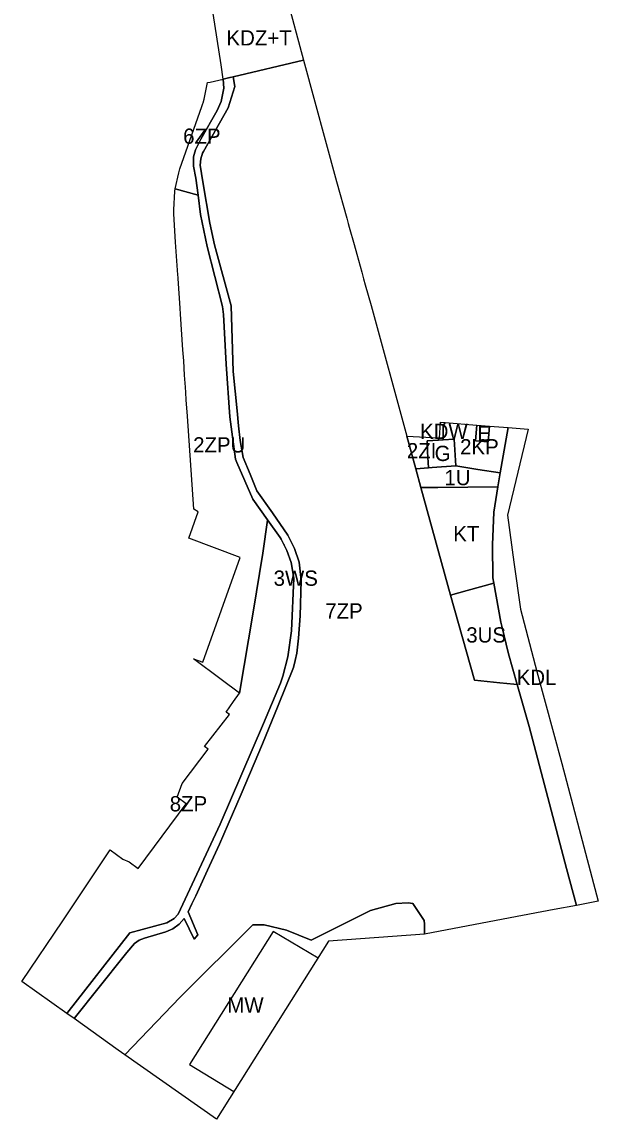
# Model space of a CAD drawing. Extents: x 7428426 to 7429844, y 5541841 to 5543687.
# Drawn here: x 7429103 to 7429555, y 5541841 to 5542703 of the extents above; entities that cross this region are included whole.
import ezdxf

# ---------------------------------------------------------------- set-up
doc = ezdxf.new("R2010")
doc.units = 0
for name, color, linetype in [('1', 7, 'Continuous'), ('linie_rozgraniczajace', 7, 'Continuous'), ('linie_zabudowy_nieprzekraczalne', 7, 'Continuous'), ('oznaczenia_przeznaczen', 7, 'Continuous')]:
    doc.layers.add(name, color=color, linetype=linetype)

msp = doc.modelspace()

# ---------------------------------------------------------------- linework, layer by layer
at = {"layer": '1'}
msp.add_lwpolyline([(7429335.26, 5541967.68), (7429299.84, 5541988.79), (7429234.14, 5541884.33), (7429269, 5541863.04)], dxfattribs=at)
at = {"layer": 'linie_rozgraniczajace'}
for points in [[(7429252.71, 5542709.77), (7429263.73, 5542712.33), (7429269.92, 5542713.77), (7429280.21, 5542716.17), (7429290.51, 5542718.57), (7429295.5, 5542719.72), (7429300.49, 5542720.88), (7429305.48, 5542722.04), (7429310.47, 5542723.2), (7429323.78, 5542673.23), (7429268.47, 5542660.17), (7429266.16, 5542659.62), (7429265.93, 5542659.56), (7429260.77, 5542658.35), (7429259, 5542669.65)], [(7429252.71, 5542709.77), (7429263.73, 5542712.33), (7429269.92, 5542713.77), (7429280.21, 5542716.17), (7429290.51, 5542718.57), (7429295.5, 5542719.72), (7429300.49, 5542720.88), (7429305.48, 5542722.04), (7429310.47, 5542723.2), (7429323.78, 5542673.23), (7429268.47, 5542660.17), (7429266.16, 5542659.62), (7429265.93, 5542659.56), (7429260.77, 5542658.35), (7429259, 5542669.65)], [(7429143.63, 5541920.29), (7429182.91, 5541969.66), (7429184.96, 5541972.29), (7429191.03, 5541979.29), (7429194.73, 5541981.82), (7429198.89, 5541983.54), (7429215.6, 5541988.57), (7429221.15, 5541990.93), (7429226.08, 5541994.41), (7429230.14, 5541998.87), (7429237.89, 5541982.83), (7429240.69, 5541986), (7429233.14, 5542004.12), (7429236.14, 5542010.42), (7429239.15, 5542016.72), (7429248.43, 5542036.98), (7429257.71, 5542057.24), (7429274.67, 5542096.7), (7429291.63, 5542136.15), (7429303.77, 5542166.16), (7429315.9, 5542196.16), (7429317.18, 5542201.74), (7429318.46, 5542207.32), (7429319.96, 5542219.28), (7429321.14, 5542236.59), (7429322.01, 5542264.55), (7429320.38, 5542278.77), (7429316.66, 5542289.62), (7429311.47, 5542300.09), (7429299.34, 5542317.53), (7429287.21, 5542334.96), (7429281.81, 5542348.02), (7429276.42, 5542361.07), (7429273.9, 5542374.36), (7429272.75, 5542386), (7429271.6, 5542397.63), (7429268.55, 5542428.61), (7429266.87, 5542480.27), (7429253.72, 5542528.1), (7429250.27, 5542545.25), (7429244.57, 5542577.78), (7429242.63, 5542590.86), (7429243.15, 5542595.67), (7429244.3, 5542600.11), (7429245.08, 5542601.55), (7429264.64, 5542635.66), (7429269.78, 5542652.45), (7429268.47, 5542660.17), (7429323.78, 5542673.23), (7429349.74, 5542578.03), (7429357.73, 5542549.11), (7429358.9, 5542544.89), (7429359.66, 5542542.13), (7429363.45, 5542528.43), (7429365.56, 5542520.79), (7429366.85, 5542516.09), (7429369.48, 5542506.62), (7429370.92, 5542501.38), (7429372.24, 5542496.62), (7429376.85, 5542480.51), (7429404.99, 5542377.87), (7429411.99, 5542352.26), (7429416.04, 5542337.44), (7429439.17, 5542253.02), (7429458.09, 5542186.04), (7429472.93, 5542184.55), (7429478.04, 5542184.04), (7429478.04, 5542184.04), (7429489.03, 5542182.94), (7429491.65, 5542182.68), (7429501.07, 5542149.66), (7429530.4, 5542038.19), (7429538.1, 5542009.2), (7429520.63, 5542005.91), (7429486.19, 5541999.43), (7429418.94, 5541986.7), (7429418.81, 5541991.25), (7429418.72, 5541994.54), (7429418.64, 5541997.49), (7429409.68, 5542010.59), (7429405.98, 5542011.25), (7429396.39, 5542010.71), (7429376.35, 5542005.34), (7429329.68, 5541981.99), (7429310.38, 5541989.74), (7429292.76, 5541993.94), (7429283.84, 5541994.08), (7429226.9, 5541937.13), (7429183.43, 5541891.96), (7429178.29, 5541895.58)], [(7429143.63, 5541920.29), (7429182.91, 5541969.66), (7429184.96, 5541972.29), (7429191.03, 5541979.29), (7429194.73, 5541981.82), (7429198.89, 5541983.54), (7429215.6, 5541988.57), (7429221.15, 5541990.93), (7429226.08, 5541994.41), (7429230.14, 5541998.87), (7429237.89, 5541982.83), (7429240.69, 5541986), (7429233.14, 5542004.12), (7429236.14, 5542010.42), (7429239.15, 5542016.72), (7429248.43, 5542036.98), (7429257.71, 5542057.24), (7429274.67, 5542096.7), (7429291.63, 5542136.15), (7429303.77, 5542166.16), (7429315.9, 5542196.16), (7429317.18, 5542201.74), (7429318.46, 5542207.32), (7429319.96, 5542219.28), (7429321.14, 5542236.59), (7429322.01, 5542264.55), (7429320.38, 5542278.77), (7429316.66, 5542289.62), (7429311.47, 5542300.09), (7429299.34, 5542317.53), (7429287.21, 5542334.96), (7429281.81, 5542348.02), (7429276.42, 5542361.07), (7429273.9, 5542374.36), (7429272.75, 5542386), (7429271.6, 5542397.63), (7429268.55, 5542428.61), (7429266.87, 5542480.27), (7429253.72, 5542528.1), (7429250.27, 5542545.25), (7429244.57, 5542577.78), (7429242.63, 5542590.86), (7429243.15, 5542595.67), (7429244.3, 5542600.11), (7429245.08, 5542601.55), (7429264.64, 5542635.66), (7429269.78, 5542652.45), (7429268.47, 5542660.17), (7429323.78, 5542673.23), (7429349.74, 5542578.03), (7429357.73, 5542549.11), (7429358.9, 5542544.89), (7429359.66, 5542542.13), (7429363.45, 5542528.43), (7429365.56, 5542520.79), (7429366.85, 5542516.09), (7429369.48, 5542506.62), (7429370.92, 5542501.38), (7429372.24, 5542496.62), (7429376.85, 5542480.51), (7429404.99, 5542377.87), (7429411.99, 5542352.26), (7429416.04, 5542337.44), (7429439.17, 5542253.02), (7429458.09, 5542186.04), (7429472.93, 5542184.55), (7429478.04, 5542184.04), (7429478.04, 5542184.04), (7429489.03, 5542182.94), (7429491.65, 5542182.68), (7429501.07, 5542149.66), (7429530.4, 5542038.19), (7429538.1, 5542009.2), (7429520.63, 5542005.91), (7429486.19, 5541999.43), (7429418.94, 5541986.7), (7429418.81, 5541991.25), (7429418.72, 5541994.54), (7429418.64, 5541997.49), (7429409.68, 5542010.59), (7429405.98, 5542011.25), (7429396.39, 5542010.71), (7429376.35, 5542005.34), (7429329.68, 5541981.99), (7429310.38, 5541989.74), (7429292.76, 5541993.94), (7429283.84, 5541994.08), (7429226.9, 5541937.13), (7429183.43, 5541891.96), (7429178.29, 5541895.58)], [(7429137.95, 5541924.34), (7429187.34, 5541987.75), (7429216.29, 5541995.64), (7429222.09, 5541998.92), (7429225.28, 5542002.42), (7429258.3, 5542073.17), (7429292.27, 5542152.24), (7429305.58, 5542183.91), (7429307.48, 5542189.25), (7429311.57, 5542204.49), (7429314.23, 5542225.01), (7429316.04, 5542266.34), (7429313.95, 5542278.73), (7429310.75, 5542287.94), (7429308.68, 5542292.34), (7429308.64, 5542292.43), (7429308.45, 5542292.77), (7429308.44, 5542292.78), (7429306.12, 5542297.06), (7429305.36, 5542298.13), (7429295.53, 5542312.05), (7429283.98, 5542328.39), (7429271.38, 5542357.15), (7429271.38, 5542357.15), (7429270.23, 5542359.78), (7429266.02, 5542393.14), (7429263.08, 5542434.38), (7429260.85, 5542473.51), (7429260.21, 5542479.64), (7429248.16, 5542526.8), (7429242.91, 5542552.08), (7429240.95, 5542567.2), (7429239.21, 5542580.6), (7429237.25, 5542589.91), (7429237.43, 5542597.24), (7429238.89, 5542602.8), (7429243.1, 5542611.16), (7429256.01, 5542633.67), (7429259.19, 5542640.81), (7429261.09, 5542651.28), (7429260.77, 5542658.35), (7429265.93, 5542659.56), (7429266.16, 5542659.62), (7429268.47, 5542660.17), (7429269.78, 5542652.45), (7429264.64, 5542635.66), (7429245.08, 5542601.55), (7429244.3, 5542600.11), (7429243.15, 5542595.67), (7429242.63, 5542590.86), (7429244.57, 5542577.78), (7429250.27, 5542545.25), (7429253.72, 5542528.1), (7429266.87, 5542480.27), (7429268.55, 5542428.61), (7429271.6, 5542397.63), (7429272.75, 5542386), (7429273.9, 5542374.36), (7429276.42, 5542361.07), (7429281.81, 5542348.02), (7429287.21, 5542334.96), (7429299.34, 5542317.53), (7429311.47, 5542300.09), (7429316.66, 5542289.62), (7429320.38, 5542278.77), (7429322.01, 5542264.55), (7429321.14, 5542236.59), (7429319.96, 5542219.28), (7429318.46, 5542207.32), (7429317.18, 5542201.74), (7429315.9, 5542196.16), (7429303.77, 5542166.16), (7429291.63, 5542136.15), (7429274.67, 5542096.7), (7429257.71, 5542057.24), (7429248.43, 5542036.98), (7429239.15, 5542016.72), (7429236.14, 5542010.42), (7429233.14, 5542004.12), (7429240.69, 5541986), (7429237.89, 5541982.83), (7429230.14, 5541998.87), (7429226.08, 5541994.41), (7429221.15, 5541990.93), (7429215.6, 5541988.57), (7429198.89, 5541983.54), (7429194.73, 5541981.82), (7429191.03, 5541979.29), (7429184.96, 5541972.29), (7429182.91, 5541969.66), (7429143.63, 5541920.29)], [(7429137.95, 5541924.34), (7429187.34, 5541987.75), (7429216.29, 5541995.64), (7429222.09, 5541998.92), (7429225.28, 5542002.42), (7429258.3, 5542073.17), (7429292.27, 5542152.24), (7429305.58, 5542183.91), (7429307.48, 5542189.25), (7429311.57, 5542204.49), (7429314.23, 5542225.01), (7429316.04, 5542266.34), (7429313.95, 5542278.73), (7429310.75, 5542287.94), (7429308.68, 5542292.34), (7429308.64, 5542292.43), (7429308.45, 5542292.77), (7429308.44, 5542292.78), (7429306.12, 5542297.06), (7429305.36, 5542298.13), (7429295.53, 5542312.05), (7429283.98, 5542328.39), (7429271.38, 5542357.15), (7429271.38, 5542357.15), (7429270.23, 5542359.78), (7429266.02, 5542393.14), (7429263.08, 5542434.38), (7429260.85, 5542473.51), (7429260.21, 5542479.64), (7429248.16, 5542526.8), (7429242.91, 5542552.08), (7429240.95, 5542567.2), (7429239.21, 5542580.6), (7429237.25, 5542589.91), (7429237.43, 5542597.24), (7429238.89, 5542602.8), (7429243.1, 5542611.16), (7429256.01, 5542633.67), (7429259.19, 5542640.81), (7429261.09, 5542651.28), (7429260.77, 5542658.35), (7429265.93, 5542659.56), (7429266.16, 5542659.62), (7429268.47, 5542660.17), (7429269.78, 5542652.45), (7429264.64, 5542635.66), (7429245.08, 5542601.55), (7429244.3, 5542600.11), (7429243.15, 5542595.67), (7429242.63, 5542590.86), (7429244.57, 5542577.78), (7429250.27, 5542545.25), (7429253.72, 5542528.1), (7429266.87, 5542480.27), (7429268.55, 5542428.61), (7429271.6, 5542397.63), (7429272.75, 5542386), (7429273.9, 5542374.36), (7429276.42, 5542361.07), (7429281.81, 5542348.02), (7429287.21, 5542334.96), (7429299.34, 5542317.53), (7429311.47, 5542300.09), (7429316.66, 5542289.62), (7429320.38, 5542278.77), (7429322.01, 5542264.55), (7429321.14, 5542236.59), (7429319.96, 5542219.28), (7429318.46, 5542207.32), (7429317.18, 5542201.74), (7429315.9, 5542196.16), (7429303.77, 5542166.16), (7429291.63, 5542136.15), (7429274.67, 5542096.7), (7429257.71, 5542057.24), (7429248.43, 5542036.98), (7429239.15, 5542016.72), (7429236.14, 5542010.42), (7429233.14, 5542004.12), (7429240.69, 5541986), (7429237.89, 5541982.83), (7429230.14, 5541998.87), (7429226.08, 5541994.41), (7429221.15, 5541990.93), (7429215.6, 5541988.57), (7429198.89, 5541983.54), (7429194.73, 5541981.82), (7429191.03, 5541979.29), (7429184.96, 5541972.29), (7429182.91, 5541969.66), (7429143.63, 5541920.29)], [(7429223.06, 5542572.26), (7429225.91, 5542584.73), (7429226.63, 5542587.83), (7429243.86, 5542636.81), (7429244.42, 5542638.41), (7429244.71, 5542639.22), (7429244.9, 5542639.75), (7429244.9, 5542639.76), (7429245.86, 5542642.49), (7429248.32, 5542655.72), (7429250.42, 5542655.88), (7429260.77, 5542658.35), (7429261.09, 5542651.28), (7429259.19, 5542640.81), (7429256.01, 5542633.67), (7429243.1, 5542611.16), (7429238.89, 5542602.8), (7429237.43, 5542597.24), (7429237.25, 5542589.91), (7429239.21, 5542580.6), (7429240.95, 5542567.2)], [(7429223.06, 5542572.26), (7429225.91, 5542584.73), (7429226.63, 5542587.83), (7429243.86, 5542636.81), (7429244.42, 5542638.41), (7429244.71, 5542639.22), (7429244.9, 5542639.75), (7429244.9, 5542639.76), (7429245.86, 5542642.49), (7429248.32, 5542655.72), (7429250.42, 5542655.88), (7429260.77, 5542658.35), (7429261.09, 5542651.28), (7429259.19, 5542640.81), (7429256.01, 5542633.67), (7429243.1, 5542611.16), (7429238.89, 5542602.8), (7429237.43, 5542597.24), (7429237.25, 5542589.91), (7429239.21, 5542580.6), (7429240.95, 5542567.2)], [(7429221.8, 5542552.53), (7429221.95, 5542555.73), (7429222.64, 5542570.45), (7429223.06, 5542572.26), (7429240.95, 5542567.2), (7429242.91, 5542552.08), (7429248.16, 5542526.8), (7429260.21, 5542479.64), (7429260.85, 5542473.51), (7429263.08, 5542434.38), (7429266.02, 5542393.14), (7429270.23, 5542359.78), (7429271.38, 5542357.15), (7429271.38, 5542357.15), (7429283.98, 5542328.39), (7429295.53, 5542312.05), (7429295.42, 5542311.98), (7429291.81, 5542286), (7429284.14, 5542239.71), (7429273.6, 5542176.05), (7429259.13, 5542186.73), (7429237.31, 5542202.84), (7429244.65, 5542200.2), (7429273.94, 5542282.45), (7429233.75, 5542297.75), (7429241.1, 5542318.33), (7429237.55, 5542320.58), (7429232.59, 5542393.61), (7429231.71, 5542406.48), (7429231.34, 5542412.03), (7429231.05, 5542416.34), (7429230.4, 5542425.82), (7429229.63, 5542437.09), (7429229.05, 5542445.75), (7429227.16, 5542473.59), (7429226.83, 5542478.42), (7429225.25, 5542501.62), (7429225.19, 5542502.47), (7429225.06, 5542504.48), (7429223.31, 5542530.23)], [(7429221.8, 5542552.53), (7429221.95, 5542555.73), (7429222.64, 5542570.45), (7429223.06, 5542572.26), (7429240.95, 5542567.2), (7429242.91, 5542552.08), (7429248.16, 5542526.8), (7429260.21, 5542479.64), (7429260.85, 5542473.51), (7429263.08, 5542434.38), (7429266.02, 5542393.14), (7429270.23, 5542359.78), (7429271.38, 5542357.15), (7429271.38, 5542357.15), (7429283.98, 5542328.39), (7429295.53, 5542312.05), (7429295.42, 5542311.98), (7429291.81, 5542286), (7429284.14, 5542239.71), (7429273.6, 5542176.05), (7429259.13, 5542186.73), (7429237.31, 5542202.84), (7429244.65, 5542200.2), (7429273.94, 5542282.45), (7429233.75, 5542297.75), (7429241.1, 5542318.33), (7429237.55, 5542320.58), (7429232.59, 5542393.61), (7429231.71, 5542406.48), (7429231.34, 5542412.03), (7429231.05, 5542416.34), (7429230.4, 5542425.82), (7429229.63, 5542437.09), (7429229.05, 5542445.75), (7429227.16, 5542473.59), (7429226.83, 5542478.42), (7429225.25, 5542501.62), (7429225.19, 5542502.47), (7429225.06, 5542504.48), (7429223.31, 5542530.23)], [(7429429.79, 5542374.8), (7429429.73, 5542376.46), (7429430.66, 5542376.4), (7429431.27, 5542388.83), (7429435.15, 5542388.51), (7429434.84, 5542388.06), (7429433.5, 5542386.14), (7429433.56, 5542375.02)], [(7429429.79, 5542374.8), (7429429.73, 5542376.46), (7429430.66, 5542376.4), (7429431.27, 5542388.83), (7429435.15, 5542388.51), (7429434.84, 5542388.06), (7429433.5, 5542386.14), (7429433.56, 5542375.02)], [(7429433.56, 5542375.02), (7429433.5, 5542386.14), (7429434.84, 5542388.06), (7429435.15, 5542388.51), (7429459.97, 5542386.51), (7429458.86, 5542374.28), (7429468.88, 5542373.37), (7429470, 5542385.7), (7429484.45, 5542384.54), (7429481.34, 5542366.78), (7429479.78, 5542357.9), (7429478.22, 5542349.01), (7429460.76, 5542351.79), (7429443.3, 5542354.56), (7429442.15, 5542375.51)], [(7429433.56, 5542375.02), (7429433.5, 5542386.14), (7429434.84, 5542388.06), (7429435.15, 5542388.51), (7429459.97, 5542386.51), (7429458.86, 5542374.28), (7429468.88, 5542373.37), (7429470, 5542385.7), (7429484.45, 5542384.54), (7429481.34, 5542366.78), (7429479.78, 5542357.9), (7429478.22, 5542349.01), (7429460.76, 5542351.79), (7429443.3, 5542354.56), (7429442.15, 5542375.51)], [(7429458.86, 5542374.28), (7429459.97, 5542386.51), (7429470, 5542385.7), (7429468.88, 5542373.37)], [(7429458.86, 5542374.28), (7429459.97, 5542386.51), (7429470, 5542385.7), (7429468.88, 5542373.37)], [(7429404.99, 5542377.87), (7429429.73, 5542376.46), (7429429.79, 5542374.8), (7429420.79, 5542374.29), (7429421.29, 5542365.65), (7429422.03, 5542353.01), (7429411.99, 5542352.26)], [(7429404.99, 5542377.87), (7429429.73, 5542376.46), (7429429.79, 5542374.8), (7429420.79, 5542374.29), (7429421.29, 5542365.65), (7429422.03, 5542353.01), (7429411.99, 5542352.26)], [(7429472.54, 5542266.6), (7429472.31, 5542292.51), (7429473.3, 5542318.09), (7429476.3, 5542338.04), (7429478.22, 5542349.01), (7429479.78, 5542357.9), (7429481.34, 5542366.78), (7429484.45, 5542384.54), (7429500.3, 5542383.26), (7429484.09, 5542315.85), (7429489.12, 5542278.85), (7429494.16, 5542241.85), (7429507.18, 5542193.07), (7429526.58, 5542120.72), (7429548.83, 5542036.28), (7429555.15, 5542012.48), (7429538.1, 5542009.2), (7429530.4, 5542038.19), (7429501.07, 5542149.66), (7429491.65, 5542182.68), (7429484.77, 5542206.79), (7429479.58, 5542228.72), (7429478.89, 5542231.67), (7429473.32, 5542262.33)], [(7429472.54, 5542266.6), (7429472.31, 5542292.51), (7429473.3, 5542318.09), (7429476.3, 5542338.04), (7429478.22, 5542349.01), (7429479.78, 5542357.9), (7429481.34, 5542366.78), (7429484.45, 5542384.54), (7429500.3, 5542383.26), (7429484.09, 5542315.85), (7429489.12, 5542278.85), (7429494.16, 5542241.85), (7429507.18, 5542193.07), (7429526.58, 5542120.72), (7429548.83, 5542036.28), (7429555.15, 5542012.48), (7429538.1, 5542009.2), (7429530.4, 5542038.19), (7429501.07, 5542149.66), (7429491.65, 5542182.68), (7429484.77, 5542206.79), (7429479.58, 5542228.72), (7429478.89, 5542231.67), (7429473.32, 5542262.33)], [(7429420.79, 5542374.29), (7429429.79, 5542374.8), (7429433.56, 5542375.02), (7429442.15, 5542375.51), (7429443.3, 5542354.56), (7429424.84, 5542353.21), (7429422.03, 5542353.01), (7429421.29, 5542365.65)], [(7429420.79, 5542374.29), (7429429.79, 5542374.8), (7429433.56, 5542375.02), (7429442.15, 5542375.51), (7429443.3, 5542354.56), (7429424.84, 5542353.21), (7429422.03, 5542353.01), (7429421.29, 5542365.65)], [(7429411.99, 5542352.26), (7429422.03, 5542353.01), (7429424.84, 5542353.21), (7429443.3, 5542354.56), (7429460.76, 5542351.79), (7429478.22, 5542349.01), (7429476.3, 5542338.04), (7429429.3, 5542337.57), (7429416.04, 5542337.44)], [(7429411.99, 5542352.26), (7429422.03, 5542353.01), (7429424.84, 5542353.21), (7429443.3, 5542354.56), (7429460.76, 5542351.79), (7429478.22, 5542349.01), (7429476.3, 5542338.04), (7429429.3, 5542337.57), (7429416.04, 5542337.44)], [(7429416.04, 5542337.44), (7429429.3, 5542337.57), (7429476.3, 5542338.04), (7429473.3, 5542318.09), (7429472.31, 5542292.51), (7429472.54, 5542266.6), (7429473.32, 5542262.33), (7429452.38, 5542256.62), (7429439.17, 5542253.02)], [(7429416.04, 5542337.44), (7429429.3, 5542337.57), (7429476.3, 5542338.04), (7429473.3, 5542318.09), (7429472.31, 5542292.51), (7429472.54, 5542266.6), (7429473.32, 5542262.33), (7429452.38, 5542256.62), (7429439.17, 5542253.02)], [(7429102.59, 5541949.54), (7429134.81, 5541997), (7429171.91, 5542053), (7429181.76, 5542045.67), (7429186.82, 5542043.46), (7429193.88, 5542038.25), (7429231.57, 5542089.1), (7429224.5, 5542094.31), (7429228.52, 5542105.01), (7429248.77, 5542132.06), (7429245.96, 5542134.14), (7429265.57, 5542159.25), (7429263.03, 5542161.1), (7429268.68, 5542169.36), (7429273.6, 5542176.05), (7429284.14, 5542239.71), (7429291.81, 5542286), (7429295.42, 5542311.98), (7429295.53, 5542312.05), (7429305.36, 5542298.13), (7429306.12, 5542297.06), (7429308.44, 5542292.78), (7429308.45, 5542292.77), (7429308.64, 5542292.43), (7429308.68, 5542292.34), (7429310.75, 5542287.94), (7429313.95, 5542278.73), (7429316.04, 5542266.34), (7429314.23, 5542225.01), (7429311.57, 5542204.49), (7429307.48, 5542189.25), (7429305.58, 5542183.91), (7429292.27, 5542152.24), (7429258.3, 5542073.17), (7429225.28, 5542002.42), (7429222.09, 5541998.92), (7429216.29, 5541995.64), (7429187.34, 5541987.75), (7429137.95, 5541924.34)], [(7429102.59, 5541949.54), (7429134.81, 5541997), (7429171.91, 5542053), (7429181.76, 5542045.67), (7429186.82, 5542043.46), (7429193.88, 5542038.25), (7429231.57, 5542089.1), (7429224.5, 5542094.31), (7429228.52, 5542105.01), (7429248.77, 5542132.06), (7429245.96, 5542134.14), (7429265.57, 5542159.25), (7429263.03, 5542161.1), (7429268.68, 5542169.36), (7429273.6, 5542176.05), (7429284.14, 5542239.71), (7429291.81, 5542286), (7429295.42, 5542311.98), (7429295.53, 5542312.05), (7429305.36, 5542298.13), (7429306.12, 5542297.06), (7429308.44, 5542292.78), (7429308.45, 5542292.77), (7429308.64, 5542292.43), (7429308.68, 5542292.34), (7429310.75, 5542287.94), (7429313.95, 5542278.73), (7429316.04, 5542266.34), (7429314.23, 5542225.01), (7429311.57, 5542204.49), (7429307.48, 5542189.25), (7429305.58, 5542183.91), (7429292.27, 5542152.24), (7429258.3, 5542073.17), (7429225.28, 5542002.42), (7429222.09, 5541998.92), (7429216.29, 5541995.64), (7429187.34, 5541987.75), (7429137.95, 5541924.34)], [(7429439.17, 5542253.02), (7429452.38, 5542256.62), (7429473.32, 5542262.33), (7429478.89, 5542231.67), (7429479.58, 5542228.72), (7429484.77, 5542206.79), (7429491.65, 5542182.68), (7429489.03, 5542182.94), (7429478.04, 5542184.04), (7429478.04, 5542184.04), (7429472.93, 5542184.55), (7429458.09, 5542186.04)], [(7429439.17, 5542253.02), (7429452.38, 5542256.62), (7429473.32, 5542262.33), (7429478.89, 5542231.67), (7429479.58, 5542228.72), (7429484.77, 5542206.79), (7429491.65, 5542182.68), (7429489.03, 5542182.94), (7429478.04, 5542184.04), (7429478.04, 5542184.04), (7429472.93, 5542184.55), (7429458.09, 5542186.04)], [(7429183.43, 5541891.96), (7429226.9, 5541937.13), (7429283.84, 5541994.08), (7429292.76, 5541993.94), (7429310.38, 5541989.74), (7429329.68, 5541981.99), (7429376.35, 5542005.34), (7429396.39, 5542010.71), (7429405.98, 5542011.25), (7429409.68, 5542010.59), (7429418.64, 5541997.49), (7429418.72, 5541994.54), (7429418.81, 5541991.25), (7429418.94, 5541986.7), (7429343.42, 5541981.06), (7429255.35, 5541841.38)], [(7429183.43, 5541891.96), (7429226.9, 5541937.13), (7429283.84, 5541994.08), (7429292.76, 5541993.94), (7429310.38, 5541989.74), (7429329.68, 5541981.99), (7429376.35, 5542005.34), (7429396.39, 5542010.71), (7429405.98, 5542011.25), (7429409.68, 5542010.59), (7429418.64, 5541997.49), (7429418.72, 5541994.54), (7429418.81, 5541991.25), (7429418.94, 5541986.7), (7429343.42, 5541981.06), (7429255.35, 5541841.38)]]:
    msp.add_lwpolyline(points, close=True, dxfattribs=at)
at = {"layer": 'linie_zabudowy_nieprzekraczalne'}
msp.add_lwpolyline([(7429335.26, 5541967.68), (7429299.84, 5541988.79), (7429234.14, 5541884.33), (7429269, 5541863.04)], dxfattribs=at)
msp.add_lwpolyline([(7429335.26, 5541967.68), (7429299.84, 5541988.79), (7429234.14, 5541884.33), (7429269, 5541863.04)], dxfattribs=at)

# ---------------------------------------------------------------- texts
at = {"layer": 'oznaczenia_przeznaczen'}
for s, p in [('KDZ+T', (7429263.26, 5542684.76)), ('KDZ+T', (7429263.26, 5542684.76)), ('KDZ+T', (7429263.26, 5542684.76)), ('KDZ+T', (7429263.26, 5542684.76)), ('6ZP', (7429229.21, 5542607.53)), ('6ZP', (7429229.21, 5542607.53)), ('6ZP', (7429229.21, 5542607.53)), ('6ZP', (7429229.21, 5542607.53)), ('KDW', (7429415.34, 5542375.63)), ('KDW', (7429415.34, 5542375.63)), ('KDW', (7429415.34, 5542375.63)), ('KDW', (7429415.34, 5542375.63)), ('E', (7429460.27, 5542373.94)), ('E', (7429460.27, 5542373.94)), ('E', (7429460.27, 5542373.94)), ('E', (7429460.27, 5542373.94)), ('2ZPU', (7429237.06, 5542365.03)), ('2ZPU', (7429237.06, 5542365.03)), ('2ZPU', (7429237.06, 5542365.03)), ('2ZPU', (7429237.06, 5542365.03)), ('2ZI', (7429404.94, 5542360.42)), ('2ZI', (7429404.94, 5542360.42)), ('2ZI', (7429404.94, 5542360.42)), ('2ZI', (7429404.94, 5542360.42)), ('G', (7429426.8, 5542358.33)), ('G', (7429426.8, 5542358.33)), ('G', (7429426.8, 5542358.33)), ('G', (7429426.8, 5542358.33)), ('2KP', (7429446.79, 5542363.54)), ('2KP', (7429446.79, 5542363.54)), ('2KP', (7429446.79, 5542363.54)), ('2KP', (7429446.79, 5542363.54)), ('1U', (7429434.47, 5542339.32)), ('1U', (7429434.47, 5542339.32)), ('1U', (7429434.47, 5542339.32)), ('1U', (7429434.47, 5542339.32)), ('KT', (7429441.4, 5542295.17)), ('KT', (7429441.4, 5542295.17)), ('KT', (7429441.4, 5542295.17)), ('KT', (7429441.4, 5542295.17)), ('3WS', (7429300.3, 5542260.31)), ('3WS', (7429300.3, 5542260.31)), ('3WS', (7429300.3, 5542260.31)), ('3WS', (7429300.3, 5542260.31)), ('7ZP', (7429340.86, 5542234.59)), ('7ZP', (7429340.86, 5542234.59)), ('7ZP', (7429340.86, 5542234.59)), ('7ZP', (7429340.86, 5542234.59)), ('3US', (7429451.62, 5542215.71)), ('3US', (7429451.62, 5542215.71)), ('3US', (7429451.62, 5542215.71)), ('3US', (7429451.62, 5542215.71)), ('KDL', (7429491.24, 5542182.31)), ('KDL', (7429491.24, 5542182.31)), ('KDL', (7429491.24, 5542182.31)), ('KDL', (7429491.24, 5542182.31)), ('8ZP', (7429218.69, 5542083.07)), ('8ZP', (7429218.69, 5542083.07)), ('8ZP', (7429218.69, 5542083.07)), ('8ZP', (7429218.69, 5542083.07)), ('MW', (7429263.94, 5541924.92)), ('MW', (7429263.94, 5541924.92)), ('MW', (7429263.94, 5541924.92)), ('MW', (7429263.94, 5541924.92))]:
    msp.add_text(s, height=12, dxfattribs=at).set_placement(p)

doc.saveas('drawing.dxf')
